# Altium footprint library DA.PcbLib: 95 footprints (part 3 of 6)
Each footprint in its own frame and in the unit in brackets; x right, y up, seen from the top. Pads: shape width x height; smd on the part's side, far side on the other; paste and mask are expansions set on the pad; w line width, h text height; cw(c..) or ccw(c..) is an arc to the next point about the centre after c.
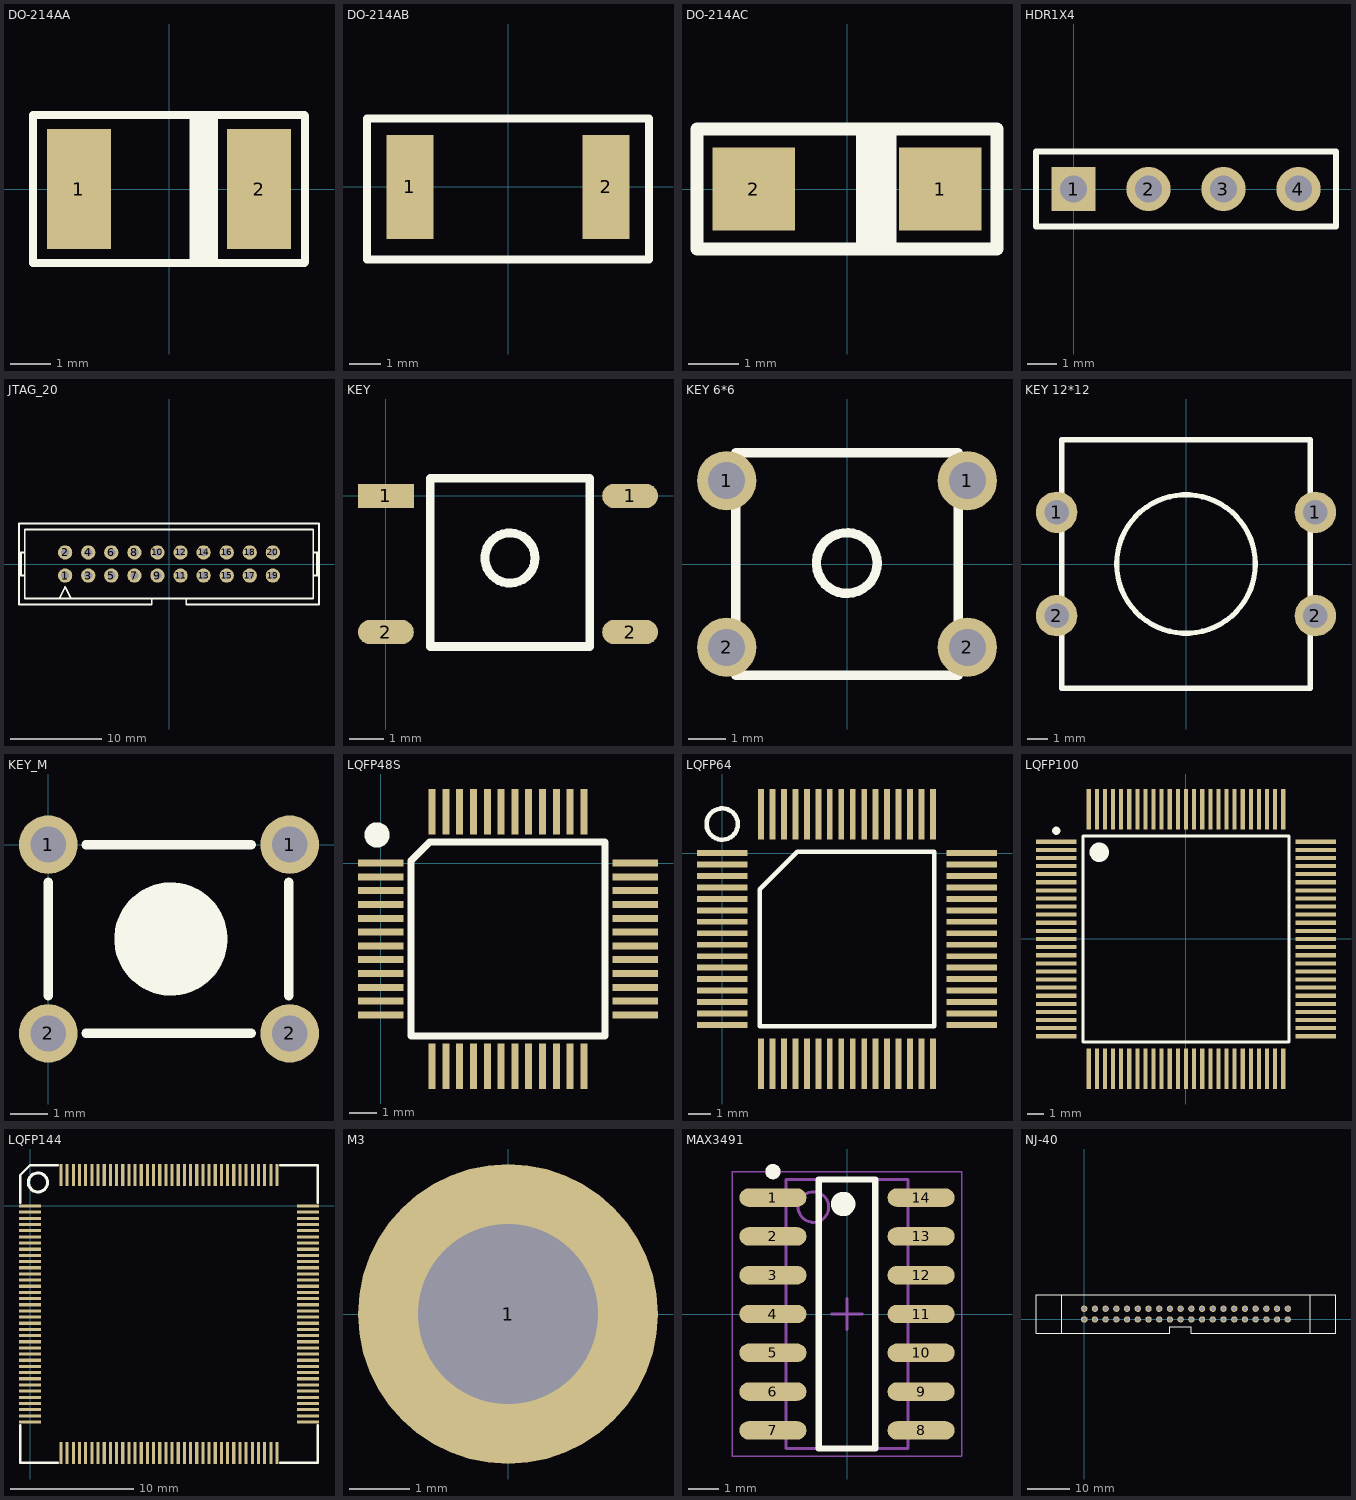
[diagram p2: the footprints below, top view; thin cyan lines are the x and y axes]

## DO-214AA [mm]
height 2.24
pads (2):
  rect 1.59x3 smd: 1(-2.25,0) 2(2.25,0)
Top Overlay:
  lines w0.2: -3.4,-1.854 -3.4,1.854 ; -3.389,-1.85 3.389,-1.85 ; -3.389,1.85 3.389,1.85 ; 3.4,-1.829 3.4,1.829
  lines w0.203: 0.61,-1.778 0.61,1.829 ; 1.118,-1.803 1.118,1.829
  lines w0.254: 0.838,-1.803 0.838,1.829 ; 0.991,-1.803 0.991,1.803
3D body: height 2.32, standoff 0.02, extent -2.7,-1.771 2.7,1.829

## DO-214AB [mm]
pads (2):
  rect 1.49x3.27 smd: 1(-3.09,0) 2(3.09,0)
Top Overlay:
  lines w0.254: -4.445,-2.286 4.445,-2.286 4.445,2.159 -4.445,2.159 -4.445,-1.905 -4.445,-2.286

## DO-214AC [mm]
pads (2):
  rect 1.655x1.67 smd: 1(1.865,0) 2(-1.865,0)
Top Overlay:
  lines w0.254: 0.305,-1.168 0.305,1.194 ; 0.508,-1.143 0.508,1.194 ; 0.737,-1.143 0.737,1.194 ; 0.864,-1.143 0.864,1.168 ; -3,-1.2 -3,1.2 3,1.2 3,-1.2 -3,-1.2
3D body: height 2.3, standoff 0.02, extent -2.743,-1.397 2.743,1.397

## HDR1X4 [mm]
pads (4):
  rect 1.5x1.5 hole 0.9: 1(0,0)
  round 1.5 hole 0.9: 2(2.54,0) 3(5.08,0) 4(7.62,0)
Top Overlay:
  lines w0.2: -1.27,-1.27 -1.27,1.27 8.89,1.27 8.89,-1.27 -1.27,-1.27

## JTAG_20 [mil]
height 149.61
pads (20):
  round 62 hole 35: 1(-450,-50) 2(-450,50) 3(-350,-50) 4(-350,50) 5(-250,-50) 6(-250,50) 7(-150,-50) 8(-150,50) 9(-50,-50) 10(-50,50) 11(50,-50) 12(50,50) 13(150,-50) 14(150,50) 15(250,-50) 16(250,50) 17(350,-50) 18(350,50) 19(450,-50) 20(450,50)
Top Overlay:
  lines w8: -650,-50 -625,-50 ; -650,50 -625,50 ; -641.67,-50 -641.67,50 ; -475,-150 -450,-100 -425,-150 ; -339.57,-175 -75,-175 -75,-150 ; -325,-175 -650,-175 -650,175 650,175 650,-175 325,-175 75,-175 75,-150 ; 625,-50 650,-50 ; 625,50 650,50 ; 641.67,-50 641.67,50 ; -75,-150 75,-150 ; -75,-150 -625,-150 -625,150 625,150 625,-150 75,-150

## KEY [mm]
pads (4):
  rect 1.6x0.7 smd: 1(0,0)
  oval 1.6x0.7 smd: 1(7,0) 2(0,-3.9) 2(7,-3.9)
Top Overlay:
  circle w0.254: c3.556,-1.778 r0.718
  lines w0.254: 1.27,-4.318 5.842,-4.318 5.842,0.508 1.27,0.508 1.27,-4.318

## KEY 6*6 [mm]
pads (4):
  round 1.6 hole 1: 1(-3.25,2.25) 1(3.25,2.25) 2(-3.25,-2.25) 2(3.25,-2.25)
Top Overlay:
  circle w0.254: c-0.006,0.025 r0.819
  lines w0.254: -3,-3 3,-3 3,3 -3,3 -3,-3

## KEY 12*12 [mm]
pads (4):
  round 2 hole 1.2: 1(-6.25,2.5) 1(6.25,2.5) 2(-6.25,-2.5) 2(6.25,-2.5)
Top Overlay:
  circle w0.254: c0,0 r3.35
  lines w0.254: -6,-6 6,-6 6,6 -6,6 -6,-6

## KEY_M [mil]
pads (4):
  round 62 hole 38: 1(0,0) 1(255.91,0) 2(0,-200) 2(255.91,-200)
Top Overlay:
  circle w60: c130,-100 r30
  lines w10: -0.03,-160 -0.03,-40 ; 39.97,-200 215,-200 ; 39.97,0 215,0 ; 255,-160 255,-40

## LQFP48S [mil] "DPIN-0.5"
height 39.37
pads (48):
  rect 65x10 smd: 1(0.42,0.29) 2(0.42,-19.39) 3(0.42,-39.08) 4(0.42,-58.76) 5(0.42,-78.45) 6(0.42,-98.13) 7(0.42,-117.82) 8(0.42,-137.5) 9(0.42,-157.19) 10(0.42,-176.87) 11(0.42,-196.56) 12(0.42,-216.24) 25(362.63,-216.24) 26(362.63,-196.56) 27(362.63,-176.87) 28(362.63,-157.19) 29(362.63,-137.5) 30(362.63,-117.82) 31(362.63,-98.13) 32(362.63,-78.45) 33(362.63,-58.76) 34(362.63,-39.08) 35(362.63,-19.39) 36(362.63,0.29)
  rect 10x65 smd: 13(73.26,-289.08) 14(92.94,-289.08) 15(112.63,-289.08) 16(132.31,-289.08) 17(152,-289.08) 18(171.68,-289.08) 19(191.37,-289.08) 20(211.05,-289.08) 21(230.74,-289.08) 22(250.42,-289.08) 23(270.11,-289.08) 24(289.79,-289.08) 37(289.79,73.13) 38(270.11,73.13) 39(250.42,73.13) 40(230.74,73.13) 41(211.05,73.13) 42(191.37,73.13) 43(171.68,73.13) 44(152,73.13) 45(132.31,73.13) 46(112.63,73.13) 47(92.94,73.13) 48(73.26,73.13)
Top Overlay:
  circle w25: c-4.93,40.29 r5.35
  lines w10: 43.73,-245.77 43.73,3.6 69.95,29.82 319.32,29.82 319.32,-245.77 43.73,-245.77

## LQFP64 [mm] "LQFP64"
height 2
pads (64):
  rect 2.2x0.254 smd: 1(0,0) 2(0,-0.5) 3(0,-1) 4(0,-1.5) 5(0,-2) 6(0,-2.5) 7(0,-3) 8(0,-3.5) 9(0,-4) 10(0,-4.5) 11(0,-5) 12(0,-5.5) 13(0,-6) 14(0,-6.5) 15(0,-7) 16(0,-7.5) 33(10.9,-7.5) 34(10.9,-7) 35(10.9,-6.5) 36(10.9,-6) 37(10.9,-5.5) 38(10.9,-5) 39(10.9,-4.5) 40(10.9,-4) 41(10.9,-3.5) 42(10.9,-3) 43(10.9,-2.5) 44(10.9,-2) 45(10.9,-1.5) 46(10.9,-1) 47(10.9,-0.5) 48(10.9,0)
  rect 0.254x2.2 smd: 17(1.7,-9.2) 18(2.2,-9.2) 19(2.7,-9.2) 20(3.2,-9.2) 21(3.7,-9.2) 22(4.2,-9.2) 23(4.7,-9.2) 24(5.2,-9.2) 25(5.7,-9.2) 26(6.2,-9.2) 27(6.7,-9.2) 28(7.2,-9.2) 29(7.7,-9.2) 30(8.2,-9.2) 31(8.7,-9.2) 32(9.2,-9.2) 49(9.2,1.7) 50(8.7,1.7) 51(8.2,1.7) 52(7.7,1.7) 53(7.2,1.7) 54(6.7,1.7) 55(6.2,1.7) 56(5.7,1.7) 57(5.2,1.7) 58(4.7,1.7) 59(4.2,1.7) 60(3.7,1.7) 61(3.2,1.7) 62(2.7,1.7) 63(2.2,1.7) 64(1.7,1.7)
Top Overlay:
  circle w0.2: c0,1.27 r0.684
  lines w0.2: 1.635,-7.565 1.635,-1.57 3.27,0.065 9.265,0.065 9.265,-7.565 1.635,-7.565

## LQFP100 [mm] "TSQFP, 100-Leads, Body 16.0x16.0mm (max), Pitch 0.50mm, IPC Medium Density"
height 1.5
pads (100):
  rect 2.5x0.254 smd: 1(-8,6) 2(-8,5.5) 3(-8,5) 4(-8,4.5) 5(-8,4) 6(-8,3.5) 7(-8,3) 8(-8,2.5) 9(-8,2) 10(-8,1.5) 11(-8,1) 12(-8,0.5) 13(-8,0) 14(-8,-0.5) 15(-8,-1) 16(-8,-1.5) 17(-8,-2) 18(-8,-2.5) 19(-8,-3) 20(-8,-3.5) 21(-8,-4) 22(-8,-4.5) 23(-8,-5) 24(-8,-5.5) 25(-8,-6) 51(8,-6) 52(8,-5.5) 53(8,-5) 54(8,-4.5) 55(8,-4) 56(8,-3.5) 57(8,-3) 58(8,-2.5) 59(8,-2) 60(8,-1.5) 61(8,-1) 62(8,-0.5) 63(8,0) 64(8,0.5) 65(8,1) 66(8,1.5) 67(8,2) 68(8,2.5) 69(8,3) 70(8,3.5) 71(8,4) 72(8,4.5) 73(8,5) 74(8,5.5) 75(8,6)
  rect 0.254x2.5 smd: 26(-6,-8) 27(-5.5,-8) 28(-5,-8) 29(-4.5,-8) 30(-4,-8) 31(-3.5,-8) 32(-3,-8) 33(-2.5,-8) 34(-2,-8) 35(-1.5,-8) 36(-1,-8) 37(-0.5,-8) 38(0,-8) 39(0.5,-8) 40(1,-8) 41(1.5,-8) 42(2,-8) 43(2.5,-8) 44(3,-8) 45(3.5,-8) 46(4,-8) 47(4.5,-8) 48(5,-8) 49(5.5,-8) 50(6,-8) 76(6,8) 77(5.5,8) 78(5,8) 79(4.5,8) 80(4,8) 81(3.5,8) 82(3,8) 83(2.5,8) 84(2,8) 85(1.5,8) 86(1,8) 87(0.5,8) 88(0,8) 89(-0.5,8) 90(-1,8) 91(-1.5,8) 92(-2,8) 93(-2.5,8) 94(-3,8) 95(-3.5,8) 96(-4,8) 97(-4.5,8) 98(-5,8) 99(-5.5,8) 100(-6,8)
Top Overlay:
  circle w0.6: c-5.35,5.35 r0.3
  circle w0.25: c-8,6.675 r0.125
  lines w0.2: -6.35,-6.35 6.35,-6.35 6.35,6.35 -6.35,6.35 -6.35,-6.35

## LQFP144 [mm]
pads (144):
  rect 1.8x0.254 smd: 1(-0.009,0.001) 2(-0.009,-0.499) 3(-0.009,-0.999) 4(-0.009,-1.499) 5(-0.009,-1.999) 6(-0.009,-2.499) 7(-0.009,-2.999) 8(-0.009,-3.499) 9(-0.009,-3.999) 10(-0.009,-4.499) 11(-0.009,-4.999) 12(-0.009,-5.499) 13(-0.009,-5.999) 14(-0.009,-6.499) 15(-0.009,-6.999) 16(-0.009,-7.499) 17(-0.009,-7.999) 18(-0.009,-8.499) 19(-0.009,-8.999) 20(-0.009,-9.499) 21(-0.009,-9.999) 22(-0.009,-10.499) 23(-0.009,-10.999) 24(-0.009,-11.499) 25(-0.009,-11.999) 26(-0.009,-12.499) 27(-0.009,-12.999) 28(-0.009,-13.499) 29(-0.009,-13.999) 30(-0.009,-14.499) 31(-0.009,-14.999) 32(-0.009,-15.499) 33(-0.009,-15.999) 34(-0.009,-16.499) 35(-0.009,-16.999) 36(-0.009,-17.499) 73(22.491,-17.499) 74(22.491,-16.999) 75(22.491,-16.499) 76(22.491,-15.999) 77(22.491,-15.499) 78(22.491,-14.999) 79(22.491,-14.499) 80(22.491,-13.999) 81(22.491,-13.499) 82(22.491,-12.999) 83(22.491,-12.499) 84(22.491,-11.999) 85(22.491,-11.499) 86(22.491,-10.999) 87(22.491,-10.499) 88(22.491,-9.999) 89(22.491,-9.499) 90(22.491,-8.999) 91(22.491,-8.499) 92(22.491,-7.999) 93(22.491,-7.499) 94(22.491,-6.999) 95(22.491,-6.499) 96(22.491,-5.999) 97(22.491,-5.499) 98(22.491,-4.999) 99(22.491,-4.499) 100(22.491,-3.999) 101(22.491,-3.499) 102(22.491,-2.999) 103(22.491,-2.499) 104(22.491,-1.999) 105(22.491,-1.499) 106(22.491,-0.999) 107(22.491,-0.499) 108(22.491,0.001)
  rect 0.254x1.8 smd: 37(2.491,-19.999) 38(2.991,-19.999) 39(3.491,-19.999) 40(3.991,-19.999) 41(4.491,-19.999) 42(4.991,-19.999) 43(5.491,-19.999) 44(5.991,-19.999) 45(6.491,-19.999) 46(6.991,-19.999) 47(7.491,-19.999) 48(7.991,-19.999) 49(8.491,-19.999) 50(8.991,-19.999) 51(9.491,-19.999) 52(9.991,-19.999) 53(10.491,-19.999) 54(10.991,-19.999) 55(11.491,-19.999) 56(11.991,-19.999) 57(12.491,-19.999) 58(12.991,-19.999) 59(13.491,-19.999) 60(13.991,-19.999) 61(14.491,-19.999) 62(14.991,-19.999) 63(15.491,-19.999) 64(15.991,-19.999) 65(16.491,-19.999) 66(16.991,-19.999) 67(17.491,-19.999) 68(17.991,-19.999) 69(18.491,-19.999) 70(18.991,-19.999) 71(19.491,-19.999) 72(19.991,-19.999) 109(19.991,2.501) 110(19.491,2.501) 111(18.991,2.501) 112(18.491,2.501) 113(17.991,2.501) 114(17.491,2.501) 115(16.991,2.501) 116(16.491,2.501) 117(15.991,2.501) 118(15.491,2.501) 119(14.991,2.501) 120(14.491,2.501) 121(13.991,2.501) 122(13.491,2.501) 123(12.991,2.501) 124(12.491,2.501) 125(11.991,2.501) 126(11.491,2.501) 127(10.991,2.501) 128(10.491,2.501) 129(9.991,2.501) 130(9.491,2.501) 131(8.991,2.501) 132(8.491,2.501) 133(7.991,2.501) 134(7.491,2.501) 135(6.991,2.501) 136(6.491,2.501) 137(5.991,2.501) 138(5.491,2.501) 139(4.991,2.501) 140(4.491,2.501) 141(3.991,2.501) 142(3.491,2.501) 143(2.991,2.501) 144(2.491,2.501)
Top Overlay:
  circle w0.254: c0.624,1.905 r0.773
  lines w0.2: -0.809,-17.749 -0.809,-20.799 2.241,-20.799 ; -0.809,0.251 -0.809,2.501 -0.009,3.301 2.241,3.301 ; 20.241,-20.799 23.291,-20.799 23.291,-17.749 ; 20.241,3.301 23.291,3.301 23.291,0.251

## M3 [mm]
pads (1):
  round 5 hole 3: 1(0,0)

## MAX3491 [mm] "TSOP, 14-Leads, Body 8.65x3.90mm, Pitch 1.27mm, IPC Medium Density"
height 1.55
pads (14):
  oval 2.2x0.6 smd: 1(-2.425,3.81) 2(-2.425,2.54) 3(-2.425,1.27) 4(-2.425,0) 5(-2.425,-1.27) 6(-2.425,-2.54) 7(-2.425,-3.81) 8(2.425,-3.81) 9(2.425,-2.54) 10(2.425,-1.27) 11(2.425,0) 12(2.425,1.27) 13(2.425,2.54) 14(2.425,3.81)
Top Overlay:
  circle w0.4: c-0.125,3.6 r0.2
  circle w0.25: c-2.425,4.66 r0.125
  lines w0.2: -0.925,-4.4 0.925,-4.4 0.925,4.4 -0.925,4.4 -0.925,-4.4
Mechanical 13:
  circle w0.1: c-1.1,3.5 r0.5
  lines w0.1: -2,-4.4 2,-4.4 2,4.4 -2,4.4 -2,-4.4
Mechanical 15:
  lines w0.05: -3.75,-4.65 3.75,-4.65 3.75,4.65 -3.75,4.65 -3.75,-4.65
  lines w0.1: -0.5,0 0.5,0 ; 0,-0.5 0,0.5
3D body: height 1.55, standoff 0.1, extent -2,-4.4 2,4.4

## NJ-40 [mm]
pads (40):
  oct 1.5x1.5 hole 1: 1(0,0)
  round 1.5 hole 1: 2(0,2.54) 3(2.54,0) 4(2.54,2.54) 5(5.08,0) 6(5.08,2.54) 7(7.62,0) 8(7.62,2.54) 9(10.16,0) 10(10.16,2.54) 11(12.7,0) 12(12.7,2.54) 13(15.24,0) 14(15.24,2.54) 15(17.78,0) 16(17.78,2.54) 17(20.32,0) 18(20.32,2.54) 19(22.86,0) 20(22.86,2.54) 21(25.4,0) 22(25.4,2.54) 23(27.94,0) 24(27.94,2.54) 25(30.48,0) 26(30.48,2.54) 27(33.02,0) 28(33.02,2.54) 29(35.56,0) 30(35.56,2.54) 31(38.1,0) 32(38.1,2.54) 33(40.64,0) 34(40.64,2.54) 35(43.18,0) 36(43.18,2.54) 37(45.72,0) 38(45.72,2.54) 39(48.26,0) 40(48.26,2.54)
Top Overlay:
  lines w0.15: -5.004,-3.26 -11.43,-3.26 -11.43,5.84 -4.978,5.84 ; 53.238,5.84 59.69,5.84 59.69,-3.26 53.264,-3.26 ; -5.3,-3.26 20.3,-3.26 20.3,-1.76 25.4,-1.76 25.4,-3.26 53.6,-3.26 53.6,5.84 -5.3,5.84 -5.3,-3.26
Bottom Overlay:
  lines w0.6: -1.041,1.27 48.62,1.27 ; 1.27,-0.813 1.27,3.556 ; 3.81,-0.813 3.81,3.556 ; 6.35,-0.813 6.35,3.556 ; 8.89,-0.813 8.89,3.556 ; 11.43,-0.813 11.43,3.556 ; 13.97,-0.813 13.97,3.556 ; 16.51,-0.813 16.51,3.556 ; 19.05,-0.813 19.05,3.556 ; 21.59,-0.813 21.59,3.556 ; 24.13,-0.813 24.13,3.556 ; 26.67,-0.813 26.67,3.556 ; 29.21,-0.813 29.21,3.556 ; 31.75,-0.813 31.75,3.556 ; 34.29,-0.813 34.29,3.556 ; 36.83,-0.813 36.83,3.556 ; 39.37,-0.813 39.37,3.556 ; 41.91,-0.813 41.91,3.556 ; 44.45,-0.813 44.45,3.556 ; 46.99,-0.838 46.99,3.531
3D body: height 23.26, standoff -2, extent -13.07,-2.997 61.889,5.903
